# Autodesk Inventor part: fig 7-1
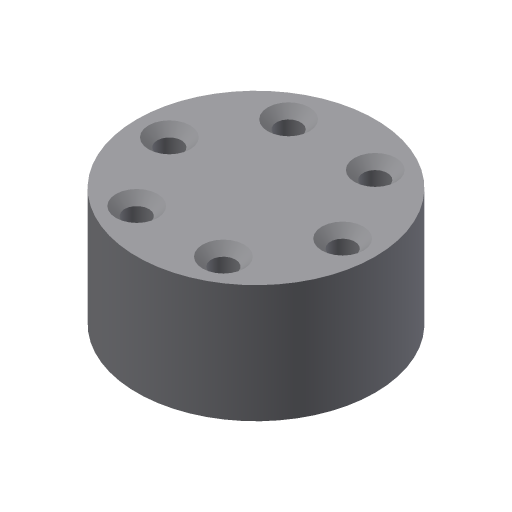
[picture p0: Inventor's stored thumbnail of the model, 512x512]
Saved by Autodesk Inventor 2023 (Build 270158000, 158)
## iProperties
Created: 2004-05
Part Number: fig 7-1
Document SubType Name: Modeling
Designer: CADCIM Technologies
Manufacturer: Standard
Standards Organization: Custom
Density: 1 g/cm^3
Material: Generic
Appearance: Default
Author: CADCIM Technologies
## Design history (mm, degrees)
sketch "Sketch1"
  geometry: C1 r 17.175 at (0, 0)
  constraints: 1 centre point
extrude "Extrusion1" new body sketch "Sketch1" distance "d0" = 17; taper "d1" = 0 deg
sketch "Sketch2"
  geometry: 1 further point
hole "Hole1" sketch "Sketch2" at (12.571, -0.074) diameter "d2" = 3.5; stored, may be unused: countersink angle "d6" = 90 deg, drill point angle "d8" = 118 deg; dims "d3" = 6, "d4" = 6, "d5" = 2, "d7" = 8
pattern_circular "Circular Pattern1" dims angle "d11" = 360 deg
body "Solid1"
